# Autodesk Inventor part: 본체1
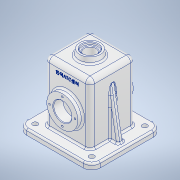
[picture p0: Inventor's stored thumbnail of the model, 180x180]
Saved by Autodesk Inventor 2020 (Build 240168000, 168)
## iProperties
Created: 2022-11
Part Number: 본체1
Material: 알루미늄 6061
Document SubType Name: Modeling
Designer: USER
Mass: 1129.8 g
Surface Area: 1015.53 cm^2
Volume: 418.444 cm^3
Density: 2.7 g/cm^3
Appearance: 알루미늄 - 평지
Author: USER
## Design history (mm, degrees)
sketch "스케치1"
  geometry: L1 (65, 62)-(-65, 62); L2 (-65, 62)-(-65, -62); L3 (-65, -62)-(65, -62); L4 (65, -62)-(65, 62); L5 (65, 62)-(-65, -62); L6 (-65, 62)-(65, -62); 1 further point
  constraints: 12 end point, 2 midpoint, 2 parallel, 1 horizontal, 1 perpendicular
  dimensions: "d0" = 130 distance of L3.end L2.end; "d1" = 124 distance of L2.end L1.end
extrude "돌출1" new body sketch "스케치1" distance "d2" = 10; taper "d3" = 0 deg
sketch "스케치2"
  geometry: L1 (-40, 40)-(40, 40); L2 (40, 40)-(40, -40); L3 (40, -40)-(-40, -40); L4 (-40, -40)-(-40, 40); L5 (-40, 40)-(40, -40); L6 (40, 40)-(-40, -40); 1 further point
  constraints: 12 end point, 2 midpoint, 2 parallel, 1 horizontal, 1 perpendicular
  dimensions: "d4" = 80 distance of L2.end L3.end; "d5" = 80 distance of L1.end L2.end
extrude "돌출2" join sketch "스케치2" distance "d6" = 107; taper "d7" = 0 deg
sketch "스케치3"
  geometry: C1 r 20 at (0, 0); 1 further point
  constraints: 1 centre point, 1 coincident
  dimensions: "d8" = 40 diameter of C1
extrude "돌출3" join sketch "스케치3" distance "d9" = 10; taper "d10" = 0 deg
sketch "스케치4"
  geometry: C1 r 14 at (0, 0); 1 further point
  constraints: 1 centre point, 1 coincident
  dimensions: "d11" = 28 diameter of C1
extrude "돌출4" cut sketch "스케치4" distance "d12" = 4; taper "d13" = 0 deg
sketch "스케치5"
  geometry: C1 r 10.5 at (0, 0); 1 further point
  constraints: 1 centre point, 1 coincident
  dimensions: "d14" = 21 diameter of C1
extrude "돌출5" cut sketch "스케치5" distance "d15" = 173; taper "d16" = 0 deg
sketch "스케치6"
  geometry: L1 (-32, 32)-(32, 32); L2 (32, 32)-(32, -32); L3 (32, -32)-(-32, -32); L4 (-32, -32)-(-32, 32); L5 (-32, 32)-(32, -32); L6 (32, 32)-(-32, -32); 1 further point
  constraints: 12 end point, 2 midpoint, 2 parallel, 1 horizontal, 1 perpendicular
  dimensions: "d17" = 64 distance of L2.end L3.end; "d18" = 64 distance of L1.end L2.end
extrude "돌출6" cut sketch "스케치6" distance "d19" = 109; taper "d20" = 0 deg
sketch "스케치7"
  geometry: C1 r 27.5 at (0, 55); 1 further point
  constraints: 1 centre point
  dimensions: "d21" = 55 diameter of C1; "d22" = 55 distance of point (0, 0) C1.centre
extrude "돌출7" join sketch "스케치7" stored distance "d23" = 98; taper "d24" = 0 deg
sketch "스케치8"
  geometry: C1 r 16 at (0, 0); 1 further point
  constraints: 1 centre point
  dimensions: "d25" = 32 diameter of C1
extrude "돌출8" cut sketch "스케치8" distance "d26" = 194; taper "d27" = 0 deg
fillet "모깎기1" dims "d28" = 15
sketch "스케치9"
  geometry: C1 r 4.5 at (-50, -47); C2 r 4.5 at (-50, 47); C3 r 4.5 at (50, -47); C4 r 4.5 at (50, 47); A1 r 15 centre (-50, -47) between (-65, -47) and (-50, -62) reference; A2 r 15 centre (-50, 47) between (-50, 62) and (-65, 47) reference; A3 r 15 centre (50, -47) between (50, -62) and (65, -47) reference; A4 r 15 centre (50, 47) between (65, 47) and (50, 62) reference; 1 further point
  constraints: 4 centre point, 4 coincident
  dimensions: "d29" = 9 diameter of C1; "d30" = 9 diameter of C2; "d31" = 9 diameter of C3; "d32" = 9 diameter of C4
extrude "돌출9" cut sketch "스케치9" distance "d33" = 231.75; taper "d34" = 0 deg
sketch "스케치10"
  geometry: L1 (50, 10)-(65, 10) reference; L2 (40, 10)-(40, 117) reference; L3 (45.5, 10)-(54.5, 10) reference; L4 (55, 10)-(40, 95.069); L5 (65, 10)-(65, 0) reference; L6 (0, 0)-(0, -32.16); L7 (-55, 10)-(-40, 95.069); L8 (-40, 10)-(-40, 117) reference; L9 (50, 10)-(-50, 10) reference; L10 (-54.5, 10)-(-45.5, 10) reference; L11 (-65, 10)-(-50, 10) reference; 1 further point
  constraints: 6 end point, 2 point on line, 2 symmetric about line, 1 vertical
  dimensions: "d37" = 10 distance from line of L5 L4.start; "d38" = 100 deg angle of L1 L4
extrude "돌출10" join sketch "스케치10" stored distance "d39" = 10; taper "d40" = 0 deg
fillet "모깎기2" dims "d41" = 3
sketch "스케치11"
  geometry: L1 (20, 127)-(-20, 127) reference; L2 (-20, 117)-(20, 117) reference; L3 (20, 117)-(18.237, 127); L4 (20, 127)-(-20, 127) reference; L5 (40, 117)-(-40, 117) reference; L6 (0, 117)-(0, 136.706); L7 (20, 117)-(20, 127) reference; 2 further points
  constraints: 4 end point, 1 midpoint, 1 point on line, 1 vertical
  dimensions: "d42" = 100 deg angle of L5 L3
revolve "회전1" sketch "스케치11" stored, may be unused: angle "d43" = 90 deg
fillet "모깎기3" dims "d44" = 3
fillet "모깎기4" dims "d45" = 3
fillet "모깎기5" dims "d46" = 3
fillet "모깎기6" dims "d47" = 3
fillet "모깎기7" dims "d48" = 8
fillet "모깎기8" dims "d49" = 8
fillet "모깎기9" dims "d50" = 3
sketch "스케치12"
  geometry: C1 r 16 at (0, 0) reference; 2 further points
  dimensions: "d51" = 22.5 distance of C1.centre point (0, 22.5)
hole "구멍1" sketch "스케치12" at (0, 22.5) diameter "d52" = 3.242; stored, may be unused: countersink angle "d56" = 90 deg, drill point angle "d58" = 118 deg; dims "d53" = 8, "d54" = 4, "d55" = 2, "d57" = 10
chamfer "모따기1" distance "d62" = 1; stored, may be unused: second distance "d63" = 2, angle "d64" = 45 deg
sketch "스케치13"
  geometry: C1 r 1.621 at (0, 22.5) reference; C2 r 17 at (0, 0) reference; 2 further points
  constraints: 1 coincident
  dimensions: "d65" = 22.5 distance of C1.centre C2.centre (derived)
hole "구멍2" sketch "스케치13" at (0, 22.5) diameter "d66" = 3.242; stored, may be unused: countersink angle "d70" = 90 deg, drill point angle "d72" = 118 deg; dims "d67" = 8, "d68" = 4, "d69" = 2, "d71" = 10
sketch "스케치14"
  geometry: L1 (29.92, 18.687)-(-29.92, 18.687); L2 (-29.92, 18.687)-(-29.92, 90.625); L3 (-29.92, 90.625)-(29.92, 90.625); L4 (29.92, 90.625)-(29.92, 18.687); 1 further point
  constraints: 8 end point, 2 parallel, 1 horizontal, 1 perpendicular
extrude "돌출11" cut sketch "스케치14" stored distance "d76" = 64; taper "d77" = 0 deg
fillet "모깎기10" dims "d78" = 3
fillet "모깎기11" dims "d79" = 3
chamfer "모따기2" distance "d80" = 1; stored, may be unused: second distance "d81" = 2, angle "d82" = 45 deg
sketch "스케치15"
  geometry: L1 (-8, 0)-(-8, -96) reference; L2 (50.237, 18)-(13.763, 18) reference; 2 further points
  constraints: 1 other
  dimensions: "d83" = 40 distance from line of L1 point (32, -7); "d84" = 25 distance from line of L2 point (32, -7)
feature "엠보싱1" sketch "스케치15" dims "d85" = 0.5, "d86" = 0
node "솔리드1"
pattern_circular "원형 패턴1" dims angle "d60" = 360 deg
pattern_circular "원형 패턴2" dims angle "d74" = 360 deg
node "투영된 루프1"
feature "A9D066F2-1C7D-4E18-AEED-F7BC21143FA4" dims "d52" = 3.242, "d53" = 8, "d54" = 4, "d55" = 2, "d56" = 90 deg, "d57" = 10, "d58" = 118 deg
